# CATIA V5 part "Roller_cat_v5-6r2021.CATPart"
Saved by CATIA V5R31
Part number: Roller
Bounding box of the stored display mesh (mm): x 0 to 20, y -10 to 10, z -10 to 10
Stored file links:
  D:\PROJECTS\Project 2021\US EDITION\CATIA V5 6R 2021\Resources\Tutorial Files\c16_catia_v5_6r2021_tut\Bearing\Roller_cat_v5-6r2021.CATPart
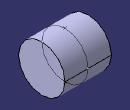
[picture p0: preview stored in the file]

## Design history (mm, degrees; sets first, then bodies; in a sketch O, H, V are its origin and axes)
Body1 (main body)
  Sketch1 on yz-plane, origin (0, 0, 0), H (0, 1, 0), V (0, 0, 1)
    circle A1 centre (0, 0) radius 10
    radius A1 = 10
  Pad1: profile Sketch1, direction (1, 0, 0), length 20
  Plane1: type Offset, RefPlane end face of Pad1, Offset -10, reversed
  Sketch2 on Plane1, origin (10, 0, 0), H (0, -1, 0), V (0, 0, 1)
    projected circle E1 centre (0, 0) radius 10 from edge [face of Pad1 from Sketch1.A1 | end face of Pad1]
    point P1 (0, -10)
    point P2 (0, 10)
    coincidence: P1 E1, P1 V, P2 V, E1 P2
